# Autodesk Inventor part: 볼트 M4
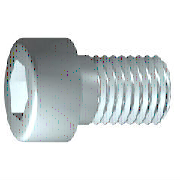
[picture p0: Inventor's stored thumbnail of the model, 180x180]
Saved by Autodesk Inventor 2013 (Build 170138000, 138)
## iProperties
IsCustomPart: 1
Created: 2012-02
Part Number: 볼트 M4
Material: 강철, 연강
Description: 6각머리 태핑 나사
Document SubType Name: Modeling
Standard: KS B 1003
Designer: mduedu
Standards Organization: KS
Language: ko-KR
Size Designation: M 4 x 12
Categories: <MemberInstance><Categories><Category DisplayName="조임쇠" InternalName="e4da775c-781d-43d5-af7c-5136215cf5a6" Mnemonic="FSTN"><Category DisplayName="볼트" InternalN
Density: 1 g/cm^3
Author: mduedu
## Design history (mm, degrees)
sketch "스케치1"
  geometry: L1 (-1, 0)-(12, 0); L2 (12, 0)-(12, 2); L3 (12, 2)-(1.75, 2); L4 (1.75, 2)-(1.32, 2); L5 (1.32, 2)-(0, 2); L6 (0, 2)-(0, 3.5); L7 (0, 3.5)-(-4, 3.5); L8 (-4, 3.5)-(-4, 1.732); L9 (-4, 1.732)-(-2, 1.732); L10 (-2, 1.732)-(-1, 0); L11 (-7.2, 0)-(15.2, 0) reference; L12 (0, -0.7)-(0, 4.2) reference; L13 (1.75, 2)-(0, 2)
  constraints: 22 end point, 6 parallel, 2 collinear, 2 perpendicular, 1 horizontal, 1 point on line
  dimensions: "d1" = 10.25 distance from line of L3.end L2 (= GEL); "d2" = 0.42952 distance of L4.end L3.end (computed from GAL); "d3" = 4 distance between parallel lines of L8 L6 (= KOH); "d4" = 2 distance of L8.end L9.end (= INTI); "d5" = 60 deg angle of L10 L1; "d6" = 4 diameter of L3 L1 (= GD); "d7" = 4 diameter of L5 L1 (= BDM); "d8" = 3.4641 diameter of L9 L1 (= 1.1547 x SW); "d9" = 7 diameter of L7 L1 (= KOD); "d26" = 12 distance between parallel lines of L12 L2 (= NLG)
revolve "본체" sketch "스케치1" stored, may be unused: angle "d10" = 90 deg
sketch "스케치2"
  geometry: L1 (0, -4.9)-(0, 4.9) reference; L2 (-4.9, 0)-(4.9, 0) reference; L3 (1.732, 0)-(0.866, -1.5); L4 (0.866, -1.5)-(-0.866, -1.5); L5 (-0.866, -1.5)-(-1.732, 0); L6 (-1.732, 0)-(-0.866, 1.5); L7 (-0.866, 1.5)-(0.866, 1.5); L8 (0.866, 1.5)-(1.732, 0); 2 further points
  constraints: 12 end point, 1 coincident, 1 horizontal alignment, 1 point on line, 12 other
extrude "슬롯" join sketch "스케치2" stored distance "d11" = 10; taper "d12" = 0 deg
workplane "Work Plane1"
fillet "Fillet2" dims "d30" = 0.1 (= R)
body "Solid1"
fillet "모깎기1" dims "d17" = 0.4 (= RR)
feature "스레드" dims "d13" = 10.25 (= GEL), "d14" = 0
chamfer "모따기1" distance "d15" = 0.42941 (= -0.5 x SPD + 0.5 x GD); stored, may be unused: second distance "d16" = 0.42941 (= GUL), angle "d27" = 45 deg
other parameters: "GD" = 4 (= NND) [user parameter; used in 2 equation terms], "NLG" = 12 [user parameter; used in 1 equation term], "GEL" = 10.25 [user parameter; used in 2 equation terms], "KOD" = 7 [user parameter; used in 1 equation term], "KOH" = 4 [user parameter; used in 1 equation term], "INTI" = 2 [user parameter; used in 1 equation term], "GAL" = 0.42941 (= 0.61345 x PTC) [user parameter; used in 1 equation term], "GUL" = 0.42941 (= 0.61345 x PTC) [user parameter; used in 1 equation term], "BDM" = 4 (= NND) [user parameter; used in 1 equation term], "SW" = 3 [user parameter; used in 2 equation terms], "RR" = 0.4 [user parameter; used in 1 equation term], "SPD" = 3.14117 (= NND - 1.2269 x PTC) [user parameter; used in 1 equation term], "d19" = 0, "d28" = 0, "d29" = 0, "R" = 0.1 [user parameter; used in 1 equation term], "PHH" = 0.2 [user parameter], "GD1" = 3.14117 (= THREADDIA - 1.2269 x PTC) [user parameter], "THREADDIA" = 4 [user parameter; used in 1 equation term], "FAWI" = 45 deg [user parameter], "TPU" = 14.28571 (computed from PTC) [user parameter], "PTC" = 0.7 [user parameter; used in 5 equation terms], "NND" = 4 [user parameter; used in 3 equation terms], "TOA" = 30 deg [user parameter], "E0" = 3.465 (= 1.155 x SW) [user parameter]
